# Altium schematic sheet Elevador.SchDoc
size A
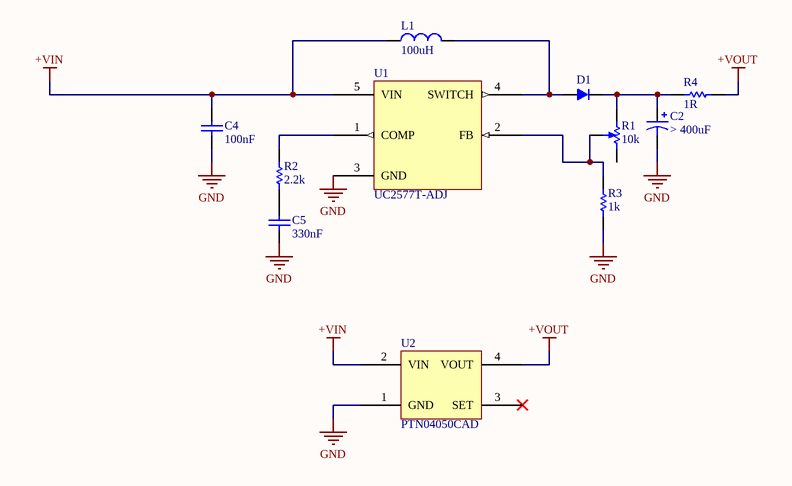
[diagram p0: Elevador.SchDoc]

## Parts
C2  > 400uF  [C 12.5 x 25]
C4  100nF  [C 1206]
C5  330nF  [C Lenteja]
D1  DIODO  [D 3528]  (value not drawn)
L1  100uH  [L SW TH]
R1  10k  [BOURNS-3596W]
R2  2.2k  [R THRU]
R3  1k  [R THRU]
R4  1R  [R 0805]
U1  UC2577T-ADJ  [TO220 5]
U2  PTN04050CAD  [PTN04050]

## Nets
+VIN: C4.2 L1.1 U1.5(VIN) U2.2(VIN)
+VOUT: R4.2 U2.4(VOUT)
GND: C2.2 C4.1 C5.1 R3.1 U1.3(GND) U2.1(GND)
NetC2_1: C2.1 D1.2(K) R1.1(CCW) R4.1
NetC5_2: C5.2 R2.1
NetD1_1: D1.1(A) L1.2 U1.4(SWITCH)
NetR1_2: R1.2(W) R3.2 U1.2(FB)
NetR2_2: R2.2 U1.1(COMP)

Not connected (* = marked no-connect by the designer): R1 3(CW); U2 3(SET)*

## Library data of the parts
C2 = C POL: Capacitor polarizado.; .Creator: SR; .PCBCheck: Used
C4 C5 = C: Capacitor; .PCBCheck: Used; .Creator: SR
D1 = DIODO: .Creator: SR
L1 = L: Inductor
R1 = 3296W-1-502: TRIMMER 5K OHM 0.5W PC PIN; Manufacturer: Bourns Inc.; Power (Watts): 0.5W, 1/2W; Tolerance: ±10%; Temperature Coefficient: ±100ppm/°C; Number of Turns: 25; Adjustment Type: Top Adjustment; Resistive Material: Cermet; .Creator: SR
R2-R4 = R: Resistencia; .Creator: SR; .PCBCheck: Used
U1 = UC2577T-ADJ: IC REG MULTI CONFIG ADJ 3A TO220; Manufacturer: Texas Instruments; Output Type: Adjustable; Number of Outputs: 1; Voltage - Output: 5 V ~ 60 V; Voltage - Input: 3 V ~ 40 V; Frequency - Switching: 52kHz; Synchronous Rectifier: No; .Creator: SR
U2 = PTN04050CAD: REG SW 5-15V 2.4A HORZ T/H; Manufacturer: Texas Instruments; Power (Watts) - Manufacture Series: 12W; Number of Outputs: 1; Voltage - Input (Min): 2.95V; Voltage - Input (Max): 5.5V; Voltage - Output 1: 5 ~ 15 V; Efficiency: 90%; .Creator: SR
